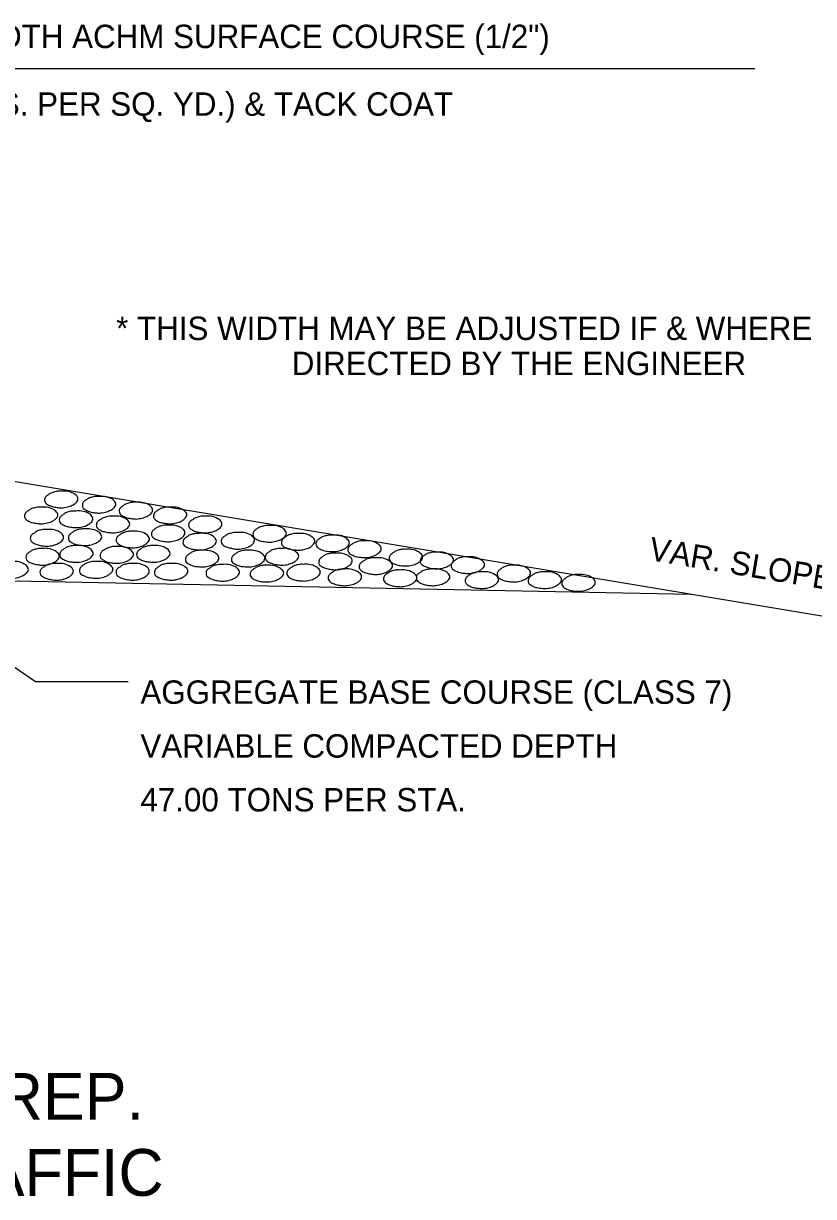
# Model space of a CAD drawing. Extents: x 1926836 to 1933254, y 596317 to 604524.
# Drawn here: x 1928640.6 to 1928843, y 601932.3 to 602233 of the extents above; entities that cross this region are included whole.
import ezdxf

# ---------------------------------------------------------------- set-up
doc = ezdxf.new("R2010")
doc.units = 0
doc.layers.add('Default', color=7, linetype='Continuous')
doc.layers.add('R_Annotation', color=7, linetype='Continuous')

msp = doc.modelspace()

# ---------------------------------------------------------------- linework, layer by layer
at = {"layer": 'Default'}
for p, q in [((1928827.98, 602221.31), (1928587.24, 602221.31)), ((1928587.24, 602124.07), (1928978.47, 602058.86)), ((1928408.64, 602094.71), (1928811.56, 602086.67))]:
    msp.add_line(p, q, dxfattribs=at)
for points in [[(1928650.26, 602113.07), (1928651.79, 602113.05), (1928653.58, 602112.43), (1928654.5, 602111.57), (1928654.61, 602111.06), (1928654.12, 602110.14), (1928653.62, 602109.74), (1928652.64, 602109.25), (1928651.15, 602108.88), (1928650.4, 602108.8), (1928649.28, 602108.91), (1928648.05, 602109.11), (1928647.08, 602109.5), (1928646.19, 602110.2), (1928646.05, 602110.8), (1928646.33, 602111.62), (1928647.02, 602112.15), (1928647.67, 602112.57), (1928648.67, 602112.91), (1928649.29, 602113.05), (1928650.26, 602113.07)], [(1928659.94, 602111.73), (1928661.43, 602111.68), (1928663.25, 602111.08), (1928664.14, 602110.23), (1928664.3, 602109.74), (1928663.8, 602108.78), (1928663.29, 602108.38), (1928662.29, 602107.9), (1928660.82, 602107.52), (1928660.08, 602107.46), (1928658.95, 602107.54), (1928657.71, 602107.76), (1928656.77, 602108.15), (1928655.87, 602108.83), (1928655.74, 602109.46), (1928655.99, 602110.27), (1928656.68, 602110.83), (1928657.32, 602111.23), (1928658.32, 602111.57), (1928658.97, 602111.68), (1928659.94, 602111.73)], [(1928669.39, 602110.23), (1928670.89, 602110.2), (1928672.73, 602109.58), (1928673.59, 602108.72), (1928673.73, 602108.21), (1928673.26, 602107.27), (1928672.74, 602106.87), (1928671.75, 602106.37), (1928670.28, 602106.03), (1928669.52, 602105.93), (1928668.41, 602106.06), (1928667.15, 602106.26), (1928666.2, 602106.65), (1928665.31, 602107.34), (1928665.17, 602107.94), (1928665.47, 602108.77), (1928666.15, 602109.31), (1928666.78, 602109.75), (1928667.77, 602110.05), (1928668.43, 602110.2), (1928669.39, 602110.23)], [(1928645.09, 602108.96), (1928646.61, 602108.94), (1928648.42, 602108.33), (1928649.32, 602107.46), (1928649.46, 602106.95), (1928648.98, 602106.03), (1928648.45, 602105.62), (1928647.48, 602105.14), (1928645.99, 602104.78), (1928645.24, 602104.69), (1928644.12, 602104.8), (1928642.89, 602105), (1928641.92, 602105.39), (1928641.05, 602106.09), (1928640.89, 602106.68), (1928641.17, 602107.51), (1928641.86, 602108.04), (1928642.5, 602108.49), (1928643.53, 602108.8), (1928644.13, 602108.94), (1928645.09, 602108.96)], [(1928654.06, 602107.97), (1928655.56, 602107.96), (1928657.36, 602107.34), (1928658.27, 602106.49), (1928658.42, 602105.96), (1928657.93, 602105.03), (1928657.4, 602104.64), (1928656.41, 602104.14), (1928654.93, 602103.8), (1928654.17, 602103.74), (1928653.05, 602103.81), (1928651.83, 602104.02), (1928650.88, 602104.41), (1928649.98, 602105.12), (1928649.82, 602105.7), (1928650.12, 602106.53), (1928650.8, 602107.07), (1928651.44, 602107.51), (1928652.46, 602107.85), (1928653.09, 602107.96), (1928654.06, 602107.97)], [(1928678.12, 602108.96), (1928679.63, 602108.94), (1928681.47, 602108.33), (1928682.36, 602107.46), (1928682.48, 602106.95), (1928682, 602106.03), (1928681.49, 602105.62), (1928680.51, 602105.14), (1928679.02, 602104.78), (1928678.26, 602104.69), (1928677.15, 602104.8), (1928675.94, 602105), (1928674.94, 602105.39), (1928674.09, 602106.09), (1928673.94, 602106.68), (1928674.23, 602107.51), (1928674.9, 602108.04), (1928675.53, 602108.49), (1928676.53, 602108.8), (1928677.17, 602108.94), (1928678.12, 602108.96)], [(1928663.5, 602106.65), (1928665.02, 602106.62), (1928666.85, 602106.01), (1928667.74, 602105.14), (1928667.87, 602104.64), (1928667.38, 602103.69), (1928666.87, 602103.3), (1928665.89, 602102.8), (1928664.41, 602102.46), (1928663.66, 602102.38), (1928662.54, 602102.47), (1928661.31, 602102.69), (1928660.34, 602103.07), (1928659.45, 602103.77), (1928659.33, 602104.36), (1928659.58, 602105.19), (1928660.28, 602105.72), (1928660.92, 602106.15), (1928661.91, 602106.49), (1928662.57, 602106.62), (1928663.5, 602106.65)], [(1928677.64, 602104.36), (1928679.15, 602104.34), (1928680.96, 602103.74), (1928681.86, 602102.88), (1928681.99, 602102.36), (1928681.5, 602101.4), (1928681, 602101.02), (1928680.02, 602100.53), (1928678.54, 602100.15), (1928677.78, 602100.09), (1928676.67, 602100.2), (1928675.43, 602100.4), (1928674.46, 602100.79), (1928673.57, 602101.48), (1928673.43, 602102.08), (1928673.71, 602102.91), (1928674.41, 602103.44), (1928675.04, 602103.86), (1928676.03, 602104.2), (1928676.69, 602104.34), (1928677.64, 602104.36)], [(1928687.14, 602106.65), (1928688.64, 602106.62), (1928690.46, 602106.01), (1928691.38, 602105.14), (1928691.49, 602104.64), (1928691.04, 602103.69), (1928690.51, 602103.3), (1928689.53, 602102.8), (1928688.05, 602102.46), (1928687.28, 602102.38), (1928686.15, 602102.47), (1928684.92, 602102.69), (1928683.98, 602103.07), (1928683.11, 602103.77), (1928682.95, 602104.36), (1928683.22, 602105.19), (1928683.92, 602105.72), (1928684.54, 602106.15), (1928685.57, 602106.49), (1928686.21, 602106.62), (1928687.14, 602106.65)], [(1928703.63, 602104.27), (1928705.14, 602104.25), (1928706.97, 602103.63), (1928707.85, 602102.75), (1928707.99, 602102.26), (1928707.5, 602101.34), (1928706.98, 602100.9), (1928705.98, 602100.43), (1928704.5, 602100.07), (1928703.76, 602100), (1928702.65, 602100.09), (1928701.4, 602100.29), (1928700.45, 602100.68), (1928699.56, 602101.38), (1928699.42, 602101.98), (1928699.7, 602102.8), (1928700.37, 602103.35), (1928701.03, 602103.8), (1928702.03, 602104.11), (1928702.68, 602104.25), (1928703.63, 602104.27)], [(1928646.58, 602103.24), (1928648.09, 602103.22), (1928649.93, 602102.6), (1928650.8, 602101.74), (1928650.94, 602101.24), (1928650.46, 602100.29), (1928649.95, 602099.89), (1928648.95, 602099.4), (1928647.48, 602099.03), (1928646.72, 602098.98), (1928645.61, 602099.06), (1928644.37, 602099.28), (1928643.4, 602099.67), (1928642.51, 602100.37), (1928642.39, 602100.95), (1928642.67, 602101.77), (1928643.36, 602102.32), (1928643.98, 602102.75), (1928644.99, 602103.1), (1928645.63, 602103.22), (1928646.58, 602103.24)], [(1928656.37, 602103.38), (1928657.85, 602103.35), (1928659.69, 602102.74), (1928660.56, 602101.87), (1928660.71, 602101.37), (1928660.22, 602100.43), (1928659.7, 602100.03), (1928658.7, 602099.54), (1928657.26, 602099.19), (1928656.46, 602099.11), (1928655.39, 602099.2), (1928654.12, 602099.4), (1928653.17, 602099.79), (1928652.28, 602100.49), (1928652.14, 602101.09), (1928652.44, 602101.93), (1928653.13, 602102.47), (1928653.73, 602102.91), (1928654.75, 602103.22), (1928655.4, 602103.35), (1928656.37, 602103.38)], [(1928668.58, 602102.8), (1928670.1, 602102.77), (1928671.9, 602102.16), (1928672.79, 602101.29), (1928672.93, 602100.82), (1928672.43, 602099.87), (1928671.92, 602099.47), (1928670.95, 602098.98), (1928669.46, 602098.61), (1928668.71, 602098.55), (1928667.6, 602098.62), (1928666.37, 602098.83), (1928665.41, 602099.22), (1928664.52, 602099.92), (1928664.36, 602100.53), (1928664.66, 602101.35), (1928665.34, 602101.91), (1928665.98, 602102.32), (1928666.96, 602102.63), (1928667.62, 602102.77), (1928668.58, 602102.8)], [(1928685.71, 602102.26), (1928687.24, 602102.22), (1928689.03, 602101.62), (1928689.93, 602100.73), (1928690.07, 602100.25), (1928689.59, 602099.31), (1928689.04, 602098.89), (1928688.09, 602098.42), (1928686.58, 602098.05), (1928685.85, 602097.99), (1928684.73, 602098.08), (1928683.51, 602098.31), (1928682.55, 602098.66), (1928681.66, 602099.37), (1928681.5, 602099.98), (1928681.78, 602100.82), (1928682.47, 602101.35), (1928683.12, 602101.77), (1928684.14, 602102.1), (1928684.74, 602102.22), (1928685.71, 602102.26)], [(1928695.48, 602102.49), (1928697.02, 602102.47), (1928698.83, 602101.85), (1928699.72, 602100.99), (1928699.83, 602100.48), (1928699.36, 602099.54), (1928698.85, 602099.14), (1928697.88, 602098.64), (1928696.38, 602098.31), (1928695.64, 602098.2), (1928694.51, 602098.33), (1928693.3, 602098.53), (1928692.33, 602098.89), (1928691.44, 602099.62), (1928691.29, 602100.21), (1928691.57, 602101.04), (1928692.25, 602101.57), (1928692.91, 602102.01), (1928693.89, 602102.32), (1928694.53, 602102.47), (1928695.48, 602102.49)], [(1928710.92, 602102.21), (1928712.43, 602102.19), (1928714.26, 602101.57), (1928715.15, 602100.7), (1928715.27, 602100.21), (1928714.79, 602099.28), (1928714.27, 602098.84), (1928713.29, 602098.38), (1928711.81, 602098), (1928711.06, 602097.95), (1928709.94, 602098.03), (1928708.71, 602098.25), (1928707.73, 602098.62), (1928706.86, 602099.33), (1928706.73, 602099.92), (1928707, 602100.73), (1928707.68, 602101.29), (1928708.34, 602101.74), (1928709.32, 602102.05), (1928709.96, 602102.19), (1928710.92, 602102.21)], [(1928719.74, 602101.8), (1928721.25, 602101.79), (1928723.08, 602101.18), (1928723.97, 602100.32), (1928724.11, 602099.82), (1928723.64, 602098.86), (1928723.09, 602098.45), (1928722.13, 602097.99), (1928720.66, 602097.63), (1928719.88, 602097.57), (1928718.78, 602097.64), (1928717.53, 602097.85), (1928716.58, 602098.25), (1928715.71, 602098.97), (1928715.55, 602099.54), (1928715.8, 602100.37), (1928716.52, 602100.9), (1928717.14, 602101.35), (1928718.17, 602101.66), (1928718.81, 602101.79), (1928719.74, 602101.8)], [(1928645.46, 602098.39), (1928646.97, 602098.38), (1928648.79, 602097.74), (1928649.71, 602096.88), (1928649.85, 602096.38), (1928649.35, 602095.45), (1928648.83, 602095.03), (1928647.86, 602094.54), (1928646.35, 602094.17), (1928645.61, 602094.12), (1928644.48, 602094.2), (1928643.26, 602094.42), (1928642.31, 602094.81), (1928641.42, 602095.51), (1928641.28, 602096.13), (1928641.55, 602096.91), (1928642.23, 602097.47), (1928642.89, 602097.91), (1928643.87, 602098.24), (1928644.49, 602098.38), (1928645.46, 602098.39)], [(1928654.11, 602099.11), (1928655.62, 602099.09), (1928657.44, 602098.45), (1928658.36, 602097.6), (1928658.5, 602097.1), (1928658, 602096.16), (1928657.47, 602095.74), (1928656.51, 602095.26), (1928655, 602094.88), (1928654.26, 602094.84), (1928653.13, 602094.92), (1928651.91, 602095.13), (1928650.96, 602095.52), (1928650.07, 602096.23), (1928649.93, 602096.85), (1928650.2, 602097.63), (1928650.88, 602098.19), (1928651.54, 602098.62), (1928652.52, 602098.95), (1928653.14, 602099.09), (1928654.11, 602099.11)], [(1928664.44, 602098.87), (1928665.95, 602098.86), (1928667.77, 602098.22), (1928668.69, 602097.36), (1928668.83, 602096.86), (1928668.33, 602095.93), (1928667.81, 602095.51), (1928666.84, 602095.03), (1928665.33, 602094.65), (1928664.6, 602094.6), (1928663.46, 602094.68), (1928662.24, 602094.9), (1928661.29, 602095.29), (1928660.4, 602095.99), (1928660.26, 602096.61), (1928660.53, 602097.39), (1928661.21, 602097.95), (1928661.87, 602098.39), (1928662.85, 602098.72), (1928663.47, 602098.86), (1928664.44, 602098.87)], [(1928673.8, 602099.11), (1928675.32, 602099.09), (1928677.14, 602098.45), (1928678.06, 602097.6), (1928678.2, 602097.1), (1928677.7, 602096.16), (1928677.17, 602095.74), (1928676.2, 602095.26), (1928674.69, 602094.88), (1928673.96, 602094.84), (1928672.82, 602094.92), (1928671.61, 602095.13), (1928670.66, 602095.52), (1928669.77, 602096.23), (1928669.63, 602096.85), (1928669.89, 602097.63), (1928670.58, 602098.19), (1928671.23, 602098.62), (1928672.22, 602098.95), (1928672.84, 602099.09), (1928673.8, 602099.11)], [(1928706.75, 602098.39), (1928708.26, 602098.38), (1928710.08, 602097.74), (1928711, 602096.88), (1928711.14, 602096.38), (1928710.64, 602095.45), (1928710.11, 602095.03), (1928709.15, 602094.54), (1928707.64, 602094.17), (1928706.9, 602094.12), (1928705.77, 602094.2), (1928704.55, 602094.42), (1928703.6, 602094.81), (1928702.71, 602095.51), (1928702.57, 602096.13), (1928702.84, 602096.91), (1928703.52, 602097.47), (1928704.18, 602097.91), (1928705.16, 602098.24), (1928705.78, 602098.38), (1928706.75, 602098.39)], [(1928727.91, 602100.32), (1928729.42, 602100.31), (1928731.24, 602099.67), (1928732.16, 602098.81), (1928732.3, 602098.31), (1928731.8, 602097.38), (1928731.27, 602096.96), (1928730.31, 602096.47), (1928728.8, 602096.1), (1928728.06, 602096.05), (1928726.93, 602096.13), (1928725.71, 602096.35), (1928724.76, 602096.74), (1928723.87, 602097.44), (1928723.73, 602098.06), (1928724, 602098.84), (1928724.68, 602099.4), (1928725.34, 602099.84), (1928726.32, 602100.17), (1928726.94, 602100.31), (1928727.91, 602100.32)], [(1928738.49, 602098.16), (1928740, 602098.14), (1928741.82, 602097.5), (1928742.74, 602096.65), (1928742.88, 602096.15), (1928742.39, 602095.21), (1928741.86, 602094.79), (1928740.89, 602094.31), (1928739.38, 602093.93), (1928738.65, 602093.89), (1928737.51, 602093.97), (1928736.29, 602094.18), (1928735.34, 602094.57), (1928734.45, 602095.27), (1928734.31, 602095.9), (1928734.58, 602096.68), (1928735.26, 602097.24), (1928735.92, 602097.67), (1928736.9, 602098), (1928737.52, 602098.14), (1928738.49, 602098.16)], [(1928637.53, 602095.03), (1928639.04, 602095.01), (1928640.86, 602094.37), (1928641.78, 602093.51), (1928641.92, 602093.01), (1928641.42, 602092.08), (1928640.89, 602091.66), (1928639.93, 602091.18), (1928638.42, 602090.8), (1928637.68, 602090.76), (1928636.55, 602090.83), (1928635.33, 602091.05), (1928634.38, 602091.44), (1928633.49, 602092.14), (1928633.35, 602092.77), (1928633.62, 602093.54), (1928634.3, 602094.11), (1928634.96, 602094.54), (1928635.94, 602094.87), (1928636.56, 602095.01), (1928637.53, 602095.03)], [(1928659.16, 602095.03), (1928660.67, 602095.01), (1928662.49, 602094.37), (1928663.41, 602093.51), (1928663.55, 602093.01), (1928663.05, 602092.08), (1928662.52, 602091.66), (1928661.56, 602091.18), (1928660.04, 602090.8), (1928659.31, 602090.76), (1928658.17, 602090.83), (1928656.96, 602091.05), (1928656.01, 602091.44), (1928655.12, 602092.14), (1928654.98, 602092.77), (1928655.25, 602093.54), (1928655.93, 602094.11), (1928656.59, 602094.54), (1928657.57, 602094.87), (1928658.19, 602095.01), (1928659.16, 602095.03)], [(1928686.3, 602097.91), (1928687.81, 602097.89), (1928689.64, 602097.25), (1928690.56, 602096.4), (1928690.7, 602095.9), (1928690.2, 602094.96), (1928689.67, 602094.54), (1928688.7, 602094.06), (1928687.19, 602093.69), (1928686.46, 602093.64), (1928685.32, 602093.72), (1928684.1, 602093.93), (1928683.15, 602094.32), (1928682.27, 602095.03), (1928682.13, 602095.65), (1928682.39, 602096.43), (1928683.08, 602096.99), (1928683.73, 602097.42), (1928684.71, 602097.75), (1928685.34, 602097.89), (1928686.3, 602097.91)], [(1928698.08, 602097.91), (1928699.59, 602097.89), (1928701.42, 602097.25), (1928702.34, 602096.4), (1928702.48, 602095.9), (1928701.98, 602094.96), (1928701.45, 602094.54), (1928700.48, 602094.06), (1928698.97, 602093.69), (1928698.24, 602093.64), (1928697.1, 602093.72), (1928695.89, 602093.93), (1928694.94, 602094.32), (1928694.05, 602095.03), (1928693.91, 602095.65), (1928694.17, 602096.43), (1928694.86, 602096.99), (1928695.51, 602097.42), (1928696.49, 602097.75), (1928697.12, 602097.89), (1928698.08, 602097.91)], [(1928720.46, 602097.19), (1928721.97, 602097.18), (1928723.79, 602096.54), (1928724.71, 602095.68), (1928724.85, 602095.18), (1928724.36, 602094.25), (1928723.83, 602093.83), (1928722.86, 602093.34), (1928721.35, 602092.97), (1928720.62, 602092.92), (1928719.48, 602093), (1928718.26, 602093.22), (1928717.31, 602093.61), (1928716.42, 602094.31), (1928716.28, 602094.93), (1928716.55, 602095.71), (1928717.23, 602096.27), (1928717.89, 602096.71), (1928718.87, 602097.04), (1928719.49, 602097.18), (1928720.46, 602097.19)], [(1928730.79, 602095.99), (1928732.3, 602095.98), (1928734.13, 602095.34), (1928735.05, 602094.48), (1928735.19, 602093.98), (1928734.69, 602093.05), (1928734.16, 602092.63), (1928733.19, 602092.14), (1928731.68, 602091.77), (1928730.95, 602091.72), (1928729.81, 602091.8), (1928728.59, 602092.02), (1928727.64, 602092.41), (1928726.76, 602093.11), (1928726.62, 602093.73), (1928726.88, 602094.51), (1928727.57, 602095.07), (1928728.22, 602095.51), (1928729.2, 602095.84), (1928729.83, 602095.98), (1928730.79, 602095.99)], [(1928746.42, 602097.44), (1928747.93, 602097.42), (1928749.76, 602096.79), (1928750.68, 602095.93), (1928750.82, 602095.43), (1928750.32, 602094.5), (1928749.79, 602094.07), (1928748.82, 602093.59), (1928747.31, 602093.22), (1928746.58, 602093.17), (1928745.44, 602093.25), (1928744.22, 602093.47), (1928743.27, 602093.86), (1928742.39, 602094.56), (1928742.25, 602095.18), (1928742.51, 602095.96), (1928743.2, 602096.52), (1928743.85, 602096.96), (1928744.83, 602097.28), (1928745.46, 602097.42), (1928746.42, 602097.44)], [(1928754.35, 602096.24), (1928755.86, 602096.23), (1928757.69, 602095.59), (1928758.61, 602094.73), (1928758.75, 602094.23), (1928758.25, 602093.3), (1928757.72, 602092.87), (1928756.75, 602092.39), (1928755.24, 602092.02), (1928754.51, 602091.97), (1928753.37, 602092.05), (1928752.16, 602092.27), (1928751.21, 602092.66), (1928750.32, 602093.36), (1928750.18, 602093.98), (1928750.44, 602094.76), (1928751.13, 602095.32), (1928751.78, 602095.76), (1928752.76, 602096.08), (1928753.39, 602096.23), (1928754.35, 602096.24)], [(1928649.06, 602094.54), (1928650.57, 602094.53), (1928652.39, 602093.89), (1928653.31, 602093.03), (1928653.45, 602092.53), (1928652.95, 602091.6), (1928652.42, 602091.18), (1928651.46, 602090.69), (1928649.95, 602090.32), (1928649.21, 602090.27), (1928648.08, 602090.35), (1928646.86, 602090.57), (1928645.91, 602090.96), (1928645.02, 602091.66), (1928644.88, 602092.28), (1928645.15, 602093.06), (1928645.83, 602093.62), (1928646.49, 602094.06), (1928647.47, 602094.39), (1928648.09, 602094.53), (1928649.06, 602094.54)], [(1928668.52, 602094.54), (1928670.03, 602094.53), (1928671.86, 602093.89), (1928672.78, 602093.03), (1928672.92, 602092.53), (1928672.42, 602091.6), (1928671.89, 602091.18), (1928670.92, 602090.69), (1928669.41, 602090.32), (1928668.68, 602090.27), (1928667.54, 602090.35), (1928666.32, 602090.57), (1928665.37, 602090.96), (1928664.49, 602091.66), (1928664.35, 602092.28), (1928664.61, 602093.06), (1928665.3, 602093.62), (1928665.95, 602094.06), (1928666.93, 602094.39), (1928667.56, 602094.53), (1928668.52, 602094.54)], [(1928678.37, 602094.54), (1928679.88, 602094.53), (1928681.71, 602093.89), (1928682.62, 602093.03), (1928682.76, 602092.53), (1928682.27, 602091.6), (1928681.74, 602091.18), (1928680.77, 602090.69), (1928679.26, 602090.32), (1928678.53, 602090.27), (1928677.39, 602090.35), (1928676.17, 602090.57), (1928675.22, 602090.96), (1928674.33, 602091.66), (1928674.19, 602092.28), (1928674.46, 602093.06), (1928675.14, 602093.62), (1928675.8, 602094.06), (1928676.78, 602094.39), (1928677.4, 602094.53), (1928678.37, 602094.54)], [(1928691.58, 602094.29), (1928693.1, 602094.28), (1928694.92, 602093.64), (1928695.84, 602092.78), (1928695.98, 602092.28), (1928695.48, 602091.35), (1928694.95, 602090.93), (1928693.98, 602090.44), (1928692.47, 602090.07), (1928691.74, 602090.02), (1928690.6, 602090.1), (1928689.39, 602090.32), (1928688.44, 602090.71), (1928687.55, 602091.41), (1928687.41, 602092.03), (1928687.67, 602092.81), (1928688.36, 602093.37), (1928689.01, 602093.81), (1928690, 602094.14), (1928690.62, 602094.28), (1928691.58, 602094.29)], [(1928702.9, 602094.06), (1928704.41, 602094.04), (1928706.23, 602093.4), (1928707.15, 602092.55), (1928707.29, 602092.05), (1928706.79, 602091.11), (1928706.26, 602090.69), (1928705.3, 602090.21), (1928703.79, 602089.84), (1928703.05, 602089.79), (1928701.92, 602089.87), (1928700.7, 602090.09), (1928699.75, 602090.47), (1928698.86, 602091.18), (1928698.72, 602091.8), (1928698.99, 602092.58), (1928699.67, 602093.14), (1928700.33, 602093.58), (1928701.31, 602093.9), (1928701.93, 602094.04), (1928702.9, 602094.06)], [(1928712.28, 602094.31), (1928713.79, 602094.29), (1928715.61, 602093.65), (1928716.53, 602092.8), (1928716.67, 602092.3), (1928716.17, 602091.36), (1928715.64, 602090.94), (1928714.68, 602090.46), (1928713.17, 602090.09), (1928712.43, 602090.04), (1928711.3, 602090.12), (1928710.08, 602090.33), (1928709.13, 602090.72), (1928708.24, 602091.43), (1928708.1, 602092.05), (1928708.37, 602092.83), (1928709.05, 602093.39), (1928709.71, 602093.83), (1928710.69, 602094.15), (1928711.31, 602094.29), (1928712.28, 602094.31)], [(1928722.86, 602093.11), (1928724.37, 602093.09), (1928726.19, 602092.45), (1928727.11, 602091.6), (1928727.25, 602091.1), (1928726.76, 602090.16), (1928726.23, 602089.74), (1928725.26, 602089.26), (1928723.75, 602088.89), (1928723.02, 602088.84), (1928721.88, 602088.92), (1928720.66, 602089.13), (1928719.71, 602089.52), (1928718.82, 602090.23), (1928718.68, 602090.85), (1928718.95, 602091.63), (1928719.63, 602092.19), (1928720.29, 602092.63), (1928721.27, 602092.95), (1928721.89, 602093.09), (1928722.86, 602093.11)], [(1928737.04, 602092.86), (1928738.55, 602092.84), (1928740.38, 602092.2), (1928741.29, 602091.35), (1928741.43, 602090.85), (1928740.94, 602089.91), (1928740.41, 602089.49), (1928739.44, 602089.01), (1928737.93, 602088.64), (1928737.2, 602088.59), (1928736.06, 602088.67), (1928734.84, 602088.89), (1928733.89, 602089.28), (1928733, 602089.98), (1928732.86, 602090.6), (1928733.13, 602091.38), (1928733.81, 602091.94), (1928734.47, 602092.38), (1928735.45, 602092.7), (1928736.07, 602092.84), (1928737.04, 602092.86)], [(1928745.46, 602093.11), (1928746.97, 602093.09), (1928748.79, 602092.45), (1928749.71, 602091.6), (1928749.85, 602091.1), (1928749.35, 602090.16), (1928748.82, 602089.74), (1928747.86, 602089.26), (1928746.34, 602088.89), (1928745.61, 602088.84), (1928744.47, 602088.92), (1928743.26, 602089.13), (1928742.31, 602089.52), (1928741.42, 602090.23), (1928741.28, 602090.85), (1928741.54, 602091.63), (1928742.23, 602092.19), (1928742.88, 602092.63), (1928743.87, 602092.95), (1928744.49, 602093.09), (1928745.46, 602093.11)], [(1928757.95, 602092.39), (1928759.46, 602092.38), (1928761.29, 602091.74), (1928762.21, 602090.88), (1928762.35, 602090.38), (1928761.85, 602089.45), (1928761.32, 602089.03), (1928760.35, 602088.54), (1928758.84, 602088.17), (1928758.11, 602088.12), (1928756.97, 602088.2), (1928755.76, 602088.42), (1928754.81, 602088.81), (1928753.92, 602089.51), (1928753.78, 602090.13), (1928754.04, 602090.91), (1928754.73, 602091.47), (1928755.38, 602091.91), (1928756.36, 602092.24), (1928756.99, 602092.38), (1928757.95, 602092.39)], [(1928766.13, 602094.07), (1928767.65, 602094.06), (1928769.47, 602093.42), (1928770.39, 602092.56), (1928770.53, 602092.06), (1928770.03, 602091.13), (1928769.5, 602090.71), (1928768.53, 602090.23), (1928767.02, 602089.85), (1928766.29, 602089.8), (1928765.15, 602089.88), (1928763.94, 602090.1), (1928762.99, 602090.49), (1928762.1, 602091.19), (1928761.96, 602091.82), (1928762.22, 602092.59), (1928762.91, 602093.16), (1928763.56, 602093.59), (1928764.54, 602093.92), (1928765.17, 602094.06), (1928766.13, 602094.07)], [(1928774.07, 602092.39), (1928775.58, 602092.38), (1928777.4, 602091.74), (1928778.32, 602090.88), (1928778.46, 602090.38), (1928777.96, 602089.45), (1928777.43, 602089.03), (1928776.47, 602088.54), (1928774.95, 602088.17), (1928774.22, 602088.12), (1928773.08, 602088.2), (1928771.87, 602088.42), (1928770.92, 602088.81), (1928770.03, 602089.51), (1928769.89, 602090.13), (1928770.15, 602090.91), (1928770.84, 602091.47), (1928771.49, 602091.91), (1928772.48, 602092.24), (1928773.1, 602092.38), (1928774.07, 602092.39)], [(1928782.71, 602091.67), (1928784.23, 602091.66), (1928786.05, 602091.02), (1928786.97, 602090.16), (1928787.11, 602089.66), (1928786.61, 602088.73), (1928786.08, 602088.31), (1928785.11, 602087.83), (1928783.6, 602087.45), (1928782.87, 602087.41), (1928781.73, 602087.48), (1928780.52, 602087.7), (1928779.57, 602088.09), (1928778.68, 602088.79), (1928778.54, 602089.42), (1928778.8, 602090.19), (1928779.49, 602090.76), (1928780.14, 602091.19), (1928781.12, 602091.52), (1928781.75, 602091.66), (1928782.71, 602091.67)]]:
    msp.add_spline(points, degree=3, dxfattribs=at)
at = {"layer": 'R_Annotation'}
msp.add_lwpolyline([(1928606.03, 602090.16), (1928643.73, 602064.3), (1928667.48, 602064.3)], dxfattribs=at)

# ---------------------------------------------------------------- texts
at = {"layer": 'Default'}
for s, height, p in [('VAR. WIDTH ACHM SURFACE COURSE (1/2")', 6, (1928603.64, 602226.64)), ('(220 LBS. PER SQ. YD.) & TACK COAT', 6, (1928606.24, 602209.3)), ('* THIS WIDTH MAY BE ADJUSTED IF & WHERE ', 6, (1928664.38, 602151.82)), ('DIRECTED BY THE ENGINEER', 6, (1928709.36, 602142.82)), ('AGGREGATE BASE COURSE (CLASS 7)', 6, (1928670.6, 602058.56)), ('VARIABLE COMPACTED DEPTH', 6, (1928670.6, 602044.77)), ('47.00 TONS PER STA.', 6, (1928670.6, 602030.98)), ('TRENCH & SHOULDER PREP.', 12, (1928443.25, 601951.94)), ('FOR MAINTENANCE OF TRAFFIC', 12, (1928422.49, 601932.44))]:
    msp.add_text(s, height=height, dxfattribs=at).set_placement(p)
msp.add_text('VAR. SLOPE (6:1 NORM.)', height=6, rotation=350.5384, dxfattribs=at).set_placement((1928800.56, 602095.45))

doc.saveas('drawing.dxf')
